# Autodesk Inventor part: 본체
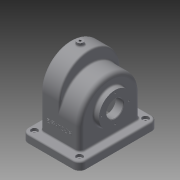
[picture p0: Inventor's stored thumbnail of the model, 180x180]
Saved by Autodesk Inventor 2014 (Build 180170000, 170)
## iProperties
Created: 2017-11
Part Number: 본체
Material: 일반
Document SubType Name: Modeling
Designer: net
Density: 1 g/cm^3
Appearance: 기본값
Mass: 398.359 g
Surface Area: 1182 cm^2
Volume: 398.359 cm^3
Author: net
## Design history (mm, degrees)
sketch "스케치1"
  geometry: L1 (0, 0)-(110, 0); L2 (110, 0)-(110, 15); L3 (110, 15)-(0, 15); L4 (0, 15)-(0, 0)
  constraints: 8 end point, 2 parallel, 1 horizontal, 1 perpendicular
  dimensions: "d0" = 110 distance of L1.start L1.end; "d1" = 15 distance of L3.end L1.start
extrude "돌출1" new body sketch "스케치1" stored distance "d2" = 150; taper "d3" = 0 deg
node "작업 평면1"
sketch "스케치2"
  geometry: L1 (0, 0)-(150, 0) reference; L2 (0, 0)-(150, 0) reference; L3 (0, 15)-(0, 0) reference; L4 (150, 15)-(0, 15) reference; L5 (150, 0)-(150, 15) reference; L6 (17, 15)-(17, 57); L7 (133, 57)-(133, 15); L8 (150, 0)-(0, 0) reference; A1 r 58 centre (75, 57) between (85.724, 0) and (64.276, 0); 3 further points
  constraints: 4 end point, 4 point on circle, 4 point on line, 2 midpoint, 2 tangent, 1 centre point, 1 parallel, 1 perpendicular, 1 vertical alignment
  dimensions: "d6" = 116 diameter of A1; "d7" = 57 distance of point (75, 0) A1.centre
extrude "돌출2" join sketch "스케치2" stored distance "d8" = 76; taper "d9" = 0 deg
sketch "스케치3"
  geometry: L1 (0, 0)-(150, 0) reference; L2 (0, 15)-(0, 0) reference; L3 (150, 15)-(0, 15) reference; L4 (150, 0)-(150, 15) reference; L5 (17, 15)-(133, 15) reference; L6 (17, 15)-(17, 57) reference; L7 (133, 57)-(133, 15) reference; L8 (17, 15)-(17, 80); L9 (133, 15)-(133, 80); L10 (17, 15)-(133, 15); A1 r 58 centre (75, 80) between (17, 80) and (133, 80); A2 r 58 centre (75, 57) between (133, 57) and (17, 57) reference; 2 further points
  constraints: 6 end point, 2 point on circle, 1 centre point, 1 collinear, 1 midpoint, 1 parallel, 1 tangent, 1 vertical alignment
  dimensions: "d10" = 116 diameter of A1; "d11" = 80 distance from line of L1 A1.centre
extrude "돌출3" join sketch "스케치3" distance "d12" = 38; taper "d13" = 0 deg
node "작업 평면2"
sketch "스케치4"
  geometry: L1 (-17, -17)-(-17, -133) reference; L2 (-17, -133)-(-93, -133) reference; L3 (-93, -133)-(-93, -17) reference; L4 (-93, -17)-(-17, -17) reference; L5 (-110, 0)-(0, 0) reference; L6 (-110, -150)-(-110, 0) reference; L7 (0, -150)-(-110, -150) reference; L8 (0, -150)-(0, 0) reference; L9 (-55, -133)-(-55, -17) reference; L10 (-93, -17)-(-55, -17) reference; L11 (-93, -133)-(-93, -17) reference; L12 (-55, -133)-(-93, -133) reference; L13 (-55, -17)-(-17, -17) reference; C1 r 6 at (-36, -75); 3 further points
  constraints: 2 midpoint, 1 centre point, 1 horizontal alignment, 1 vertical alignment
  dimensions: "d15" = 12 diameter of C1
extrude "돌출4" join sketch "스케치4" stored distance "d16" = 38; taper "d17" = 0 deg
sketch "스케치5"
  geometry: L1 (150, 15)-(0, 15) reference; L2 (0, 0)-(0, 15) reference; L3 (150, 0)-(0, 0) reference; L4 (150, 15)-(150, 0) reference; L5 (150, 0)-(0, 0) reference; C1 r 31 at (75, 65); 2 further points
  constraints: 1 centre point, 1 midpoint, 1 vertical alignment
  dimensions: "d18" = 65 distance from line of C1.centre L3; "d19" = 62 diameter of C1
extrude "돌출5" join sketch "스케치5" distance "d20" = 10; taper "d21" = 0 deg
sketch "스케치6"
  geometry: L1 (0, 0)-(-150, 0) reference; L2 (0, 15)-(0, 0) reference; L3 (-150, 15)-(0, 15) reference; L4 (-150, 0)-(-150, 15) reference; L5 (0, 0)-(-150, 0) reference; C1 r 37.5 at (-75, 65); 3 further points
  constraints: 2 midpoint, 1 centre point, 1 vertical alignment
  dimensions: "d22" = 75 diameter of C1; "d23" = 65 distance from line of C1.centre L1
extrude "돌출6" join sketch "스케치6" distance "d24" = 9; taper "d25" = 0 deg
node "작업 평면3"
sketch "스케치8"
  geometry: L1 (17, 15)-(133, 15) reference; L2 (17, 15)-(17, 80) reference; L3 (133, 80)-(133, 15) reference; L4 (22, 80)-(22, 20); L5 (128, 20)-(128, 80); L6 (22, 20)-(22, -3.891); L7 (128, -3.891)-(128, 20); L8 (22, -3.891)-(128, -3.891); C1 r 37.5 at (75, 65) reference; A1 r 58 centre (75, 80) between (133, 80) and (17, 80) reference; A2 r 53 centre (75, 80) between (128, 80) and (22, 80); 2 further points
  constraints: 10 end point, 2 perpendicular, 2 point on circle, 1 centre point, 1 parallel, 1 vertical alignment, 1 other
  dimensions: "d37" = 5 distance between parallel lines of L4 L2; "d38" = 5 distance between parallel lines of L5 L3; "d39" = 18.8909 distance between parallel lines of L1 L8
extrude "돌출7" cut sketch "스케치8" distance "d40" = 28; taper "d41" = 0 deg
node "작업 평면4"
sketch "스케치9"
  geometry: L1 (0, 0)-(150, 0) reference; L2 (0, 15)-(0, 0) reference; L3 (150, 15)-(0, 15) reference; L4 (150, 0)-(150, 15) reference; L5 (133, 80)-(133, 15) reference; L6 (17, 15)-(17, 80) reference; L7 (22, -7.753)-(22, 57); L8 (128, 57)-(128, -7.753); L9 (22, -7.753)-(128, -7.753); A1 r 58 centre (75, 57) between (133, 57) and (17, 57) reference; A2 r 53 centre (75, 57) between (128, 57) and (22, 57); 1 further point
  constraints: 6 end point, 3 parallel, 2 point on circle, 1 centre point, 1 perpendicular
  dimensions: "d43" = 5 distance between parallel lines of L7 L6; "d44" = 5 distance between parallel lines of L5 L8; "d45" = 5 radial gap between concentric circles of A1 A2; "d46" = 7.75265 distance between parallel lines of L1 L9
extrude "돌출8" cut sketch "스케치9" distance "d47" = 28; taper "d49" = 0 deg; dims "d48" = 14, "d50" = 0
hole "구멍1" diameter "d53" = 32; stored, may be unused: countersink angle "d57" = 90 deg, drill point angle "d59" = 118 deg; dims "d51" = 10, "d52" = 10, "d54" = 6, "d55" = 4, "d56" = 2, "d58" = 8
sketch "스케치10"
  geometry: C1 r 16 at (0, 0) reference; 2 further points
  constraints: 1 vertical alignment
  dimensions: "d60" = 26 distance of point (0, 26) C1.centre
hole "구멍2" sketch "스케치10" at (0, 26) diameter "d61" = 2.459; stored, may be unused: countersink angle "d65" = 90 deg, drill point angle "d67" = 118 deg; dims "d62" = 6, "d63" = 4, "d64" = 2, "d66" = 8
sketch "스케치11"
  geometry: C1 r 16 at (0, 0) reference; 2 further points
  constraints: 1 vertical alignment
  dimensions: "d71" = 29 distance of point (0, 29) C1.centre
hole "구멍3" sketch "스케치11" at (0, 29) diameter "d72" = 2.459; stored, may be unused: countersink angle "d76" = 90 deg, drill point angle "d78" = 118 deg; dims "d73" = 6, "d74" = 4, "d75" = 2, "d77" = 8
hole "구멍4" diameter "d84" = 4.134; stored, may be unused: countersink angle "d88" = 90 deg, drill point angle "d90" = 118 deg; dims "d85" = 6, "d86" = 4, "d87" = 2, "d89" = 8, "d120" = 10, "d121" = 10
sketch "스케치12"
  geometry: L1 (110, 0)-(0, 0) reference; L2 (0, 150)-(0, 0) reference; 2 further points
  dimensions: "d92" = 12 distance from line of point (12, 12) L1; "d93" = 12 distance from line of L2 point (12, 12)
fillet "모깎기1" dims "d91" = 12
hole "구멍5" sketch "스케치12" diameter "d94" = 5; stored, may be unused: countersink angle "d98" = 90 deg, drill point angle "d100" = 118 deg; dims "d95" = 6, "d96" = 12, "d97" = 5, "d99" = 8
chamfer "모따기1" distance "d107" = 1; stored, may be unused: second distance "d108" = 2, angle "d109" = 45 deg
fillet "모깎기2" dims "d110" = 3
fillet "모깎기3" dims "d111" = 3
fillet "모깎기4" dims "d112" = 3
fillet "모깎기6" dims "d114" = 8
fillet "모깎기7" dims "d115" = 3
sketch "스케치13"
  geometry: L1 (-35, 23)-(-35, -39) reference; L2 (-40, -57)-(46, -57) reference; 2 further points
  constraints: 1 other
  dimensions: "d116" = 38 distance from line of point (3, -17) L1; "d117" = 40 distance from line of point (3, -17) L2
feature "엠보싱1" sketch "스케치13" dims "d118" = 0.5, "d119" = 0
fillet "모깎기5" dims "d113" = 3
sketch "스케치7"
  geometry: L1 (17, 138)-(17, 80) reference; L2 (17, 27.5)-(17, 102.5) reference; L3 (17, 80)-(17, 15) reference; L4 (93, 15)-(93, 57) reference; L5 (93, 96)-(93, 34) reference; L6 (93, 57)-(93, 115) reference; L7 (55, 115)-(93, 115) reference; L8 (55, 80)-(55, 138) reference; L9 (55, 138)-(17, 138) reference; L10 (50, 133)-(22, 133); L11 (22, 133)-(22, 0); L12 (50, 0)-(50, 133); L13 (50, 110)-(88, 110); L14 (88, 0)-(88, 110); L15 (88, 57)-(50, 57); L16 (50, 80)-(22, 80); L17 (110, 0)-(0, 0) reference; L18 (22, 0)-(88, 0)
  constraints: 16 end point, 5 parallel, 5 point on line, 3 perpendicular, 2 collinear
  dimensions: "d26" = 5 distance between parallel lines of L7 L13; "d27" = 5 distance between parallel lines of L14 L6; "d28" = 5 distance between parallel lines of L10 L9; "d29" = 5 distance between parallel lines of L11 L1; "d30" = 5 distance between parallel lines of L8 L12; "d31" = 57 distance between parallel lines of L17 L15; "d32" = 80 distance between parallel lines of L16 L17
revolve "회전1" stored, may be unused: angle "d33" = 90 deg
revolve "회전2" stored, may be unused: angle "d34" = 90 deg
node "솔리드1"
pattern_circular "원형 패턴1" dims angle "d69" = 360 deg
pattern_circular "원형 패턴2" dims angle "d80" = 360 deg
pattern_linear "직사각형 패턴1" dims "d103" = 86, "d106" = 126
node "투영된 루프1"
node "투영된 루프2"
node "투영된 루프3"
node "투영된 루프4"
node "투영된 루프5"
node "투영된 루프6"
node "투영된 루프7"
node "투영된 루프8"
node "투영된 루프9"
other parameters: "d14" = -144, "d35" = -5, "d42" = 5
